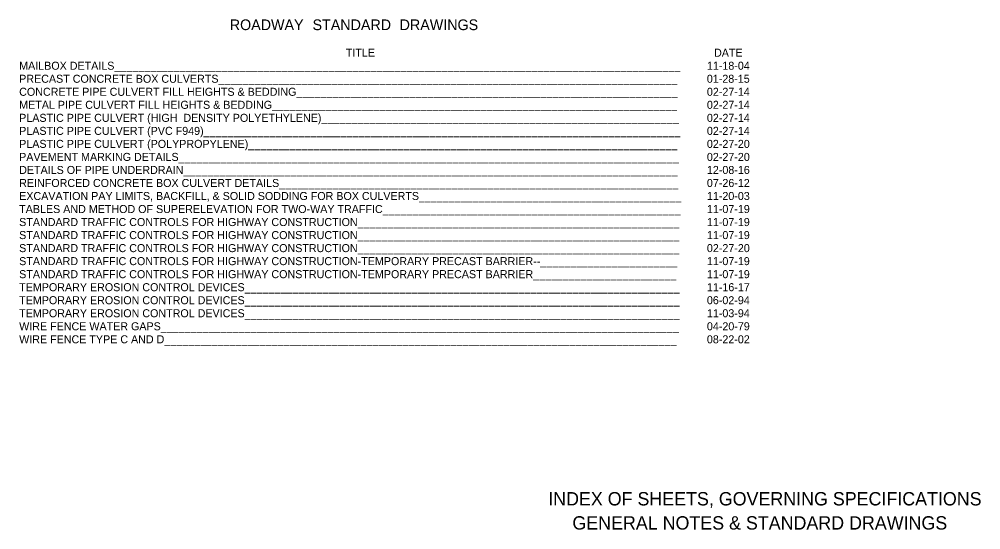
# Model space of a CAD drawing. Extents: x -1197 to 1681, y -1031 to 1021.
# Drawn here: x 179 to 1620, y -1031 to -267 of the extents above; entities that cross this region are included whole.
import ezdxf

# ---------------------------------------------------------------- set-up
doc = ezdxf.new("R2010")
doc.units = 0
doc.layers.add('Default', color=7, linetype='Continuous')
doc.layers.add('R_Border', color=7, linetype='Continuous')

msp = doc.modelspace()

# ---------------------------------------------------------------- texts
at = {"layer": 'Default'}
for s, height, p in [('ROADWAY', 16, (494.8, -283.2)), (' STANDARD', 16, (612.9, -283.2)), (' DRAWINGS', 16, (743.4, -283.2)), ('TITLE', 12, (668.7, -323)), ('DATE', 12, (1220.5, -323)), ('MAILBOX DETAILS_______________________________________________________________________________________________', 12, (179.2, -342.5)), ('11-18-04', 12, (1209.8, -342.5)), ('PRECAST CONCRETE BOX CULVERTS_____________________________________________________________________________', 12, (179.2, -362)), ('01-28-15', 12, (1209.7, -362)), ('CONCRETE PIPE CULVERT FILL HEIGHTS & BEDDING________________________________________________________________', 12, (179.2, -381.5)), ('02-27-14', 12, (1209.8, -381.5)), ('METAL PIPE CULVERT FILL HEIGHTS & BEDDING____________________________________________________________________', 12, (179.2, -401)), ('02-27-14', 12, (1209.8, -401)), ('PLASTIC PIPE CULVERT (HIGH  DENSITY POLYETHYLENE)____________________________________________________________', 12, (179.2, -420.5)), ('02-27-14', 12, (1209.8, -420.5)), ('PLASTIC PIPE CULVERT (PVC F949)________________________________________________________________________________', 12, (179.2, -440)), ('02-27-14', 12, (1209.8, -440)), ('PLASTIC PIPE CULVERT (POLYPROPYLENE)________________________________________________________________________', 12, (179.2, -459.5)), ('02-27-20', 12, (1209.8, -459.5)), ('PAVEMENT MARKING DETAILS____________________________________________________________________________________', 12, (179.2, -479)), ('02-27-20', 12, (1209.8, -479)), ('DETAILS OF PIPE UNDERDRAIN___________________________________________________________________________________', 12, (179.2, -498.5)), ('12-08-16', 12, (1209.8, -498.5)), ('REINFORCED CONCRETE BOX CULVERT DETAILS___________________________________________________________________', 12, (179.2, -518)), ('07-26-12', 12, (1209.8, -518)), ('EXCAVATION PAY LIMITS, BACKFILL, & SOLID SODDING FOR BOX CULVERTS____________________________________________', 12, (179.2, -537.5)), ('11-20-03', 12, (1209.8, -537.5)), ('TABLES AND METHOD OF SUPERELEVATION FOR TWO-WAY TRAFFIC__________________________________________________', 12, (179.2, -557)), ('11-07-19', 12, (1209.8, -557)), ('STANDARD TRAFFIC CONTROLS FOR HIGHWAY CONSTRUCTION______________________________________________________', 12, (179.2, -576.5)), ('11-07-19', 12, (1209.8, -576.5)), ('STANDARD TRAFFIC CONTROLS FOR HIGHWAY CONSTRUCTION______________________________________________________', 12, (179.2, -596)), ('11-07-19', 12, (1209.8, -596)), ('STANDARD TRAFFIC CONTROLS FOR HIGHWAY CONSTRUCTION______________________________________________________', 12, (179.2, -615.5)), ('02-27-20', 12, (1209.8, -615.5)), ('STANDARD TRAFFIC CONTROLS FOR HIGHWAY CONSTRUCTION-TEMPORARY PRECAST BARRIER--_______________________', 12, (179.2, -635)), ('11-07-19', 12, (1209.8, -635)), ('STANDARD TRAFFIC CONTROLS FOR HIGHWAY CONSTRUCTION-TEMPORARY PRECAST BARRIER________________________', 12, (179.2, -654.5)), ('11-07-19', 12, (1209.8, -654.5)), ('TEMPORARY EROSION CONTROL DEVICES_________________________________________________________________________', 12, (179.2, -674)), ('11-16-17', 12, (1209.8, -674)), ('TEMPORARY EROSION CONTROL DEVICES_________________________________________________________________________', 12, (179.2, -693.5)), ('06-02-94', 12, (1209.8, -693.5)), ('TEMPORARY EROSION CONTROL DEVICES_________________________________________________________________________', 12, (179.2, -713)), ('11-03-94', 12, (1209.8, -713)), ('WIRE FENCE WATER GAPS_______________________________________________________________________________________', 12, (179.2, -732.5)), ('04-20-79', 12, (1209.8, -732.5)), ('WIRE FENCE TYPE C AND D______________________________________________________________________________________', 12, (179.2, -752)), ('08-22-02', 12, (1209.8, -752))]:
    msp.add_text(s, height=height, dxfattribs=at).set_placement(p)
at = {"layer": 'R_Border'}
for s, p in [('INDEX OF SHEETS, GOVERNING SPECIFICATIONS', (972, -994.7)), ('GENERAL NOTES & STANDARD DRAWINGS', (1008.2, -1030.8))]:
    msp.add_text(s, height=20, dxfattribs=at).set_placement(p)

doc.saveas('drawing.dxf')
